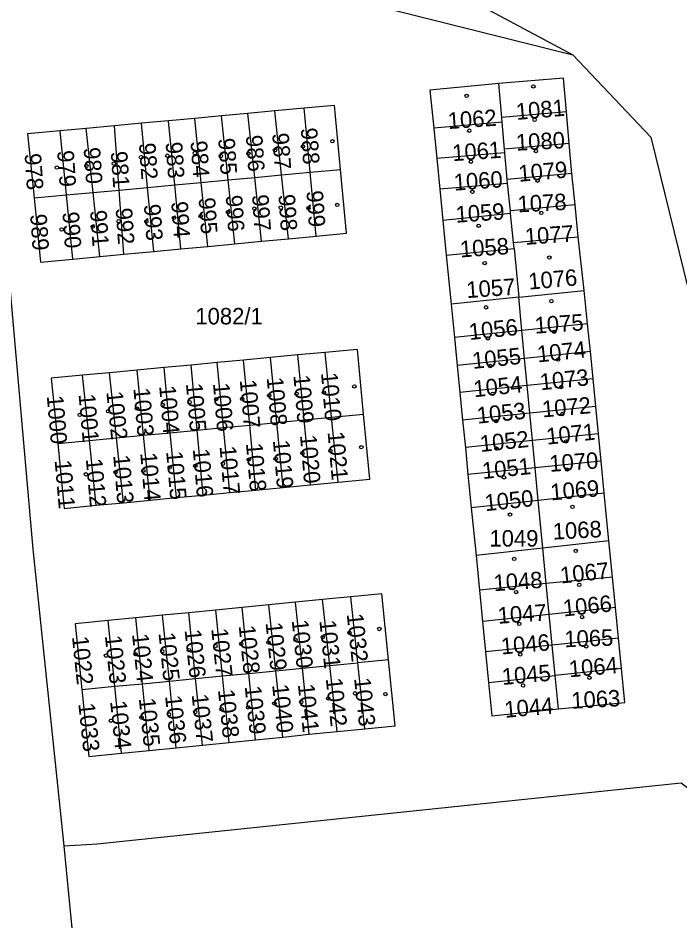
# Model space of a CAD drawing. Extents: x -869103 to -863415, y -1015889 to -1012477.
# Drawn here: x -866491.1 to -866422.9, y -1013922.4 to -1013829.3 of the extents above; entities that cross this region are included whole.
import ezdxf

# ---------------------------------------------------------------- set-up
doc = ezdxf.new("R2010")
doc.units = 0
for name, color, linetype in [('Hranice parcel', 7, 'Continuous'), ('Parcelní čísla', 7, 'Continuous'), ('Značky budov', 7, 'Continuous')]:
    doc.layers.add(name, color=color, linetype=linetype)

msp = doc.modelspace()

# ---------------------------------------------------------------- linework, layer by layer
at = {"layer": 'Hranice parcel'}
for p, q in [((-866467.18, -1013824.71), (-866433.93, -1013833.04)), ((-866441.25, -1013839.52), (-866441.57, -1013836.02)), ((-866464.66, -1013838.83), (-866467.43, -1013839.09)), ((-866461.63, -1013838.55), (-866464.66, -1013838.83)), ((-866463.96, -1013845.43), (-866464.66, -1013838.83)), ((-866461, -1013845.15), (-866461.63, -1013838.55)), ((-866434.58, -1013838.93), (-866441.25, -1013839.52)), ((-866434.29, -1013842.18), (-866434.58, -1013838.93)), ((-866475.62, -1013839.85), (-866478.42, -1013840.11)), ((-866472.92, -1013839.6), (-866475.62, -1013839.85)), ((-866474.98, -1013846.46), (-866475.62, -1013839.85)), ((-866470.16, -1013839.34), (-866472.92, -1013839.6)), ((-866472.24, -1013846.2), (-866472.92, -1013839.6)), ((-866467.43, -1013839.09), (-866470.16, -1013839.34)), ((-866469.47, -1013845.94), (-866470.16, -1013839.34)), ((-866466.72, -1013845.69), (-866467.43, -1013839.09)), ((-866441.21, -1013839.98), (-866448.27, -1013840.62)), ((-866441.21, -1013839.98), (-866441.25, -1013839.52)), ((-866440.96, -1013842.79), (-866441.21, -1013839.98)), ((-866484.1, -1013840.64), (-866486.78, -1013840.89)), ((-866486.14, -1013847.5), (-866486.78, -1013840.89)), ((-866481.2, -1013840.37), (-866484.1, -1013840.64)), ((-866483.4, -1013847.24), (-866484.1, -1013840.64)), ((-866478.42, -1013840.11), (-866481.2, -1013840.37)), ((-866480.71, -1013846.99), (-866481.2, -1013840.37)), ((-866477.78, -1013846.72), (-866478.42, -1013840.11)), ((-866448.27, -1013840.62), (-866447.96, -1013843.75)), ((-866434.29, -1013842.18), (-866440.96, -1013842.79)), ((-866434.03, -1013845.27), (-866434.29, -1013842.18)), ((-866440.94, -1013843.15), (-866447.96, -1013843.75)), ((-866440.94, -1013843.15), (-866440.96, -1013842.79)), ((-866440.7, -1013845.92), (-866440.94, -1013843.15)), ((-866447.96, -1013843.75), (-866447.65, -1013846.89)), ((-866466.72, -1013845.69), (-866463.96, -1013845.43)), ((-866463.96, -1013845.43), (-866461, -1013845.15)), ((-866463.26, -1013852.01), (-866463.96, -1013845.43)), ((-866461, -1013845.15), (-866457.87, -1013844.86)), ((-866460.38, -1013851.74), (-866461, -1013845.15)), ((-866434.03, -1013845.27), (-866440.7, -1013845.92)), ((-866433.7, -1013848.51), (-866434.03, -1013845.27)), ((-866477.78, -1013846.72), (-866474.98, -1013846.46)), ((-866474.98, -1013846.46), (-866472.24, -1013846.2)), ((-866474.35, -1013853.06), (-866474.98, -1013846.46)), ((-866472.24, -1013846.2), (-866469.47, -1013845.94)), ((-866471.57, -1013852.8), (-866472.24, -1013846.2)), ((-866469.47, -1013845.94), (-866466.72, -1013845.69)), ((-866468.78, -1013852.53), (-866469.47, -1013845.94)), ((-866466.02, -1013852.27), (-866466.72, -1013845.69)), ((-866440.67, -1013846.31), (-866447.65, -1013846.89)), ((-866440.67, -1013846.31), (-866440.7, -1013845.92)), ((-866440.37, -1013849.14), (-866440.67, -1013846.31)), ((-866486.14, -1013847.5), (-866483.4, -1013847.24)), ((-866483.4, -1013847.24), (-866480.71, -1013846.99)), ((-866482.7, -1013853.85), (-866483.4, -1013847.24)), ((-866480.71, -1013846.99), (-866477.78, -1013846.72)), ((-866480.22, -1013853.62), (-866480.71, -1013846.99)), ((-866477.14, -1013853.32), (-866477.78, -1013846.72)), ((-866447.65, -1013846.89), (-866447.33, -1013850.12)), ((-866489.49, -1013847.81), (-866486.14, -1013847.5)), ((-866485.49, -1013854.11), (-866486.14, -1013847.5)), ((-866433.7, -1013848.51), (-866440.37, -1013849.14)), ((-866440.34, -1013849.4), (-866440.37, -1013849.14)), ((-866433.38, -1013851.81), (-866433.7, -1013848.51)), ((-866440.34, -1013849.4), (-866447.33, -1013850.12)), ((-866447.33, -1013850.12), (-866446.98, -1013853.7)), ((-866440.05, -1013852.41), (-866440.34, -1013849.4)), ((-866466.02, -1013852.27), (-866463.26, -1013852.01)), ((-866463.26, -1013852.01), (-866460.38, -1013851.74)), ((-866440.05, -1013852.41), (-866433.38, -1013851.81)), ((-866432.74, -1013857.36), (-866433.38, -1013851.81)), ((-866474.35, -1013853.06), (-866471.57, -1013852.8)), ((-866471.57, -1013852.8), (-866468.78, -1013852.53)), ((-866468.78, -1013852.53), (-866466.02, -1013852.27)), ((-866439.99, -1013853.02), (-866440.05, -1013852.41)), ((-866485.49, -1013854.11), (-866482.7, -1013853.85)), ((-866482.7, -1013853.85), (-866480.22, -1013853.62)), ((-866480.22, -1013853.62), (-866477.14, -1013853.32)), ((-866477.14, -1013853.32), (-866474.35, -1013853.06)), ((-866446.98, -1013853.7), (-866439.99, -1013853.02)), ((-866446.98, -1013853.7), (-866446.48, -1013858.77)), ((-866439.99, -1013853.02), (-866439.51, -1013858.05)), ((-866439.51, -1013858.05), (-866432.74, -1013857.36)), ((-866432.4, -1013860.79), (-866432.74, -1013857.36)), ((-866439.51, -1013858.05), (-866446.48, -1013858.77)), ((-866439.18, -1013861.49), (-866439.51, -1013858.05)), ((-866446.48, -1013858.77), (-866446.14, -1013862.21)), ((-866432.4, -1013860.79), (-866439.18, -1013861.49)), ((-866432.12, -1013863.63), (-866432.4, -1013860.79)), ((-866439.18, -1013861.49), (-866446.14, -1013862.21)), ((-866446.14, -1013862.21), (-866445.85, -1013865.09)), ((-866438.9, -1013864.35), (-866439.18, -1013861.49)), ((-866462.29, -1013864), (-866465.11, -1013864.27)), ((-866459.46, -1013863.73), (-866462.29, -1013864)), ((-866461.64, -1013870.68), (-866462.29, -1013864)), ((-866458.8, -1013870.41), (-866459.46, -1013863.73)), ((-866432.12, -1013863.63), (-866438.9, -1013864.35)), ((-866431.84, -1013866.46), (-866432.12, -1013863.63)), ((-866473.3, -1013865.04), (-866476.08, -1013865.3)), ((-866470.59, -1013864.78), (-866473.3, -1013865.04)), ((-866472.68, -1013871.75), (-866473.3, -1013865.04)), ((-866467.88, -1013864.53), (-866470.59, -1013864.78)), ((-866469.94, -1013871.49), (-866470.59, -1013864.78)), ((-866465.11, -1013864.27), (-866467.88, -1013864.53)), ((-866467.25, -1013871.23), (-866467.88, -1013864.53)), ((-866464.46, -1013870.96), (-866465.11, -1013864.27)), ((-866438.9, -1013864.35), (-866445.85, -1013865.09)), ((-866445.85, -1013865.09), (-866445.58, -1013867.88)), ((-866438.63, -1013867.16), (-866438.9, -1013864.35)), ((-866481.69, -1013865.83), (-866484.48, -1013866.09)), ((-866478.86, -1013865.56), (-866481.69, -1013865.83)), ((-866480.98, -1013872.55), (-866481.69, -1013865.83)), ((-866476.08, -1013865.3), (-866478.86, -1013865.56)), ((-866478.19, -1013872.28), (-866478.86, -1013865.56)), ((-866475.44, -1013872.02), (-866476.08, -1013865.3)), ((-866483.78, -1013872.82), (-866484.48, -1013866.09)), ((-866431.84, -1013866.46), (-866438.63, -1013867.16)), ((-866431.56, -1013869.3), (-866431.84, -1013866.46)), ((-866438.63, -1013867.16), (-866445.58, -1013867.88)), ((-866445.58, -1013867.88), (-866445.3, -1013870.71)), ((-866438.36, -1013870), (-866438.63, -1013867.16)), ((-866431.56, -1013869.3), (-866438.36, -1013870)), ((-866431.28, -1013872.13), (-866431.56, -1013869.3)), ((-866464.46, -1013870.96), (-866461.64, -1013870.68)), ((-866461.64, -1013870.68), (-866458.8, -1013870.41)), ((-866460.99, -1013877.4), (-866461.64, -1013870.68)), ((-866458.8, -1013870.41), (-866455.5, -1013870.09)), ((-866458.14, -1013877.12), (-866458.8, -1013870.41)), ((-866438.36, -1013870), (-866445.3, -1013870.71)), ((-866445.3, -1013870.71), (-866445.01, -1013873.55)), ((-866438.09, -1013872.83), (-866438.36, -1013870)), ((-866472.68, -1013871.75), (-866469.94, -1013871.49)), ((-866469.94, -1013871.49), (-866467.25, -1013871.23)), ((-866469.29, -1013878.19), (-866469.94, -1013871.49)), ((-866467.25, -1013871.23), (-866464.46, -1013870.96)), ((-866466.61, -1013877.93), (-866467.25, -1013871.23)), ((-866463.81, -1013877.66), (-866464.46, -1013870.96)), ((-866483.78, -1013872.82), (-866480.98, -1013872.55)), ((-866480.98, -1013872.55), (-866478.19, -1013872.28)), ((-866480.27, -1013879.24), (-866480.98, -1013872.55)), ((-866478.19, -1013872.28), (-866475.44, -1013872.02)), ((-866477.52, -1013878.97), (-866478.19, -1013872.28)), ((-866475.44, -1013872.02), (-866472.68, -1013871.75)), ((-866474.8, -1013878.71), (-866475.44, -1013872.02)), ((-866472.06, -1013878.45), (-866472.68, -1013871.75)), ((-866431.28, -1013872.13), (-866438.09, -1013872.83)), ((-866431, -1013874.97), (-866431.28, -1013872.13)), ((-866487.05, -1013873.14), (-866483.78, -1013872.82)), ((-866483.09, -1013879.5), (-866483.78, -1013872.82)), ((-866438.09, -1013872.83), (-866445.01, -1013873.55)), ((-866437.82, -1013875.64), (-866438.09, -1013872.83)), ((-866445.01, -1013873.55), (-866444.74, -1013876.33)), ((-866431, -1013874.97), (-866437.82, -1013875.64)), ((-866430.68, -1013878.25), (-866431, -1013874.97)), ((-866437.82, -1013875.64), (-866444.74, -1013876.33)), ((-866437.5, -1013879), (-866437.82, -1013875.64)), ((-866460.99, -1013877.4), (-866458.14, -1013877.12)), ((-866444.74, -1013876.33), (-866444.4, -1013879.76)), ((-866469.29, -1013878.19), (-866466.61, -1013877.93)), ((-866466.61, -1013877.93), (-866463.81, -1013877.66)), ((-866463.81, -1013877.66), (-866460.99, -1013877.4)), ((-866480.27, -1013879.24), (-866477.52, -1013878.97)), ((-866477.52, -1013878.97), (-866474.8, -1013878.71)), ((-866474.8, -1013878.71), (-866472.06, -1013878.45)), ((-866472.06, -1013878.45), (-866469.29, -1013878.19)), ((-866437.5, -1013879), (-866444.4, -1013879.76)), ((-866430.68, -1013878.25), (-866437.5, -1013879)), ((-866437.02, -1013883.93), (-866437.5, -1013879)), ((-866430.2, -1013883.17), (-866430.68, -1013878.25)), ((-866483.09, -1013879.5), (-866480.27, -1013879.24)), ((-866444.4, -1013879.76), (-866443.91, -1013884.69)), ((-866430.2, -1013883.17), (-866437.02, -1013883.93)), ((-866429.83, -1013886.9), (-866430.2, -1013883.17)), ((-866437.02, -1013883.93), (-866443.91, -1013884.69)), ((-866436.67, -1013887.58), (-866437.02, -1013883.93)), ((-866443.91, -1013884.69), (-866443.56, -1013888.27)), ((-866429.83, -1013886.9), (-866436.67, -1013887.58)), ((-866429.52, -1013890.03), (-866429.83, -1013886.9)), ((-866436.67, -1013887.58), (-866443.56, -1013888.27)), ((-866443.56, -1013888.27), (-866443.24, -1013891.5)), ((-866436.36, -1013890.76), (-866436.67, -1013887.58)), ((-866459.73, -1013889.23), (-866462.53, -1013889.5)), ((-866456.81, -1013888.94), (-866459.73, -1013889.23)), ((-866458.99, -1013896.03), (-866459.73, -1013889.23)), ((-866456.09, -1013895.75), (-866456.81, -1013888.94)), ((-866468.02, -1013890.04), (-866470.74, -1013890.31)), ((-866465.27, -1013889.77), (-866468.02, -1013890.04)), ((-866467.34, -1013896.84), (-866468.02, -1013890.04)), ((-866462.53, -1013889.5), (-866465.27, -1013889.77)), ((-866464.56, -1013896.57), (-866465.27, -1013889.77)), ((-866461.82, -1013896.31), (-866462.53, -1013889.5)), ((-866429.52, -1013890.03), (-866436.36, -1013890.76)), ((-866429.21, -1013893.22), (-866429.52, -1013890.03)), ((-866478.98, -1013891.12), (-866481.83, -1013891.4)), ((-866476.24, -1013890.85), (-866478.98, -1013891.12)), ((-866478.3, -1013897.9), (-866478.98, -1013891.12)), ((-866473.51, -1013890.58), (-866476.24, -1013890.85)), ((-866475.53, -1013897.63), (-866476.24, -1013890.85)), ((-866470.74, -1013890.31), (-866473.51, -1013890.58)), ((-866472.82, -1013897.37), (-866473.51, -1013890.58)), ((-866470.06, -1013897.1), (-866470.74, -1013890.31)), ((-866436.36, -1013890.76), (-866443.24, -1013891.5)), ((-866436.06, -1013893.92), (-866436.36, -1013890.76)), ((-866481.16, -1013898.17), (-866481.83, -1013891.4)), ((-866443.24, -1013891.5), (-866442.93, -1013894.63)), ((-866436.06, -1013893.92), (-866442.93, -1013894.63)), ((-866429.21, -1013893.22), (-866436.06, -1013893.92)), ((-866435.76, -1013897.05), (-866436.06, -1013893.92)), ((-866428.9, -1013896.33), (-866429.21, -1013893.22)), ((-866442.93, -1013894.63), (-866442.62, -1013897.77)), ((-866458.99, -1013896.03), (-866456.09, -1013895.75)), ((-866452.93, -1013895.45), (-866456.09, -1013895.75)), ((-866455.37, -1013902.55), (-866456.09, -1013895.75)), ((-866467.34, -1013896.84), (-866464.56, -1013896.57)), ((-866464.56, -1013896.57), (-866461.82, -1013896.31)), ((-866463.84, -1013903.4), (-866464.56, -1013896.57)), ((-866461.82, -1013896.31), (-866458.99, -1013896.03)), ((-866461.11, -1013903.12), (-866461.82, -1013896.31)), ((-866458.24, -1013902.84), (-866458.99, -1013896.03)), ((-866428.9, -1013896.33), (-866435.76, -1013897.05)), ((-866478.3, -1013897.9), (-866475.53, -1013897.63)), ((-866475.53, -1013897.63), (-866472.82, -1013897.37)), ((-866474.82, -1013904.5), (-866475.53, -1013897.63)), ((-866472.82, -1013897.37), (-866470.06, -1013897.1)), ((-866472.12, -1013904.23), (-866472.82, -1013897.37)), ((-866470.06, -1013897.1), (-866467.34, -1013896.84)), ((-866469.38, -1013903.95), (-866470.06, -1013897.1)), ((-866466.66, -1013903.68), (-866467.34, -1013896.84)), ((-866442.62, -1013897.77), (-866435.76, -1013897.05)), ((-866435.42, -1013900.51), (-866435.76, -1013897.05)), ((-866484.55, -1013898.5), (-866481.16, -1013898.17)), ((-866481.16, -1013898.17), (-866478.3, -1013897.9)), ((-866480.48, -1013905.06), (-866481.16, -1013898.17)), ((-866477.61, -1013904.78), (-866478.3, -1013897.9)), ((-866463.84, -1013903.4), (-866461.11, -1013903.12)), ((-866461.11, -1013903.12), (-866458.24, -1013902.84)), ((-866458.24, -1013902.84), (-866455.37, -1013902.55)), ((-866474.82, -1013904.5), (-866472.12, -1013904.23)), ((-866472.12, -1013904.23), (-866469.38, -1013903.95)), ((-866469.38, -1013903.95), (-866466.66, -1013903.68)), ((-866466.66, -1013903.68), (-866463.84, -1013903.4)), ((-866480.48, -1013905.06), (-866477.61, -1013904.78)), ((-866477.61, -1013904.78), (-866474.82, -1013904.5)), ((-866479.31, -1013987.71), (-866486.37, -1013914.62))]:
    msp.add_line(p, q, dxfattribs=at)
for points in [[(-866491.13, -1013799.65), (-866474.29, -1013811.45), (-866433.93, -1013833.04)], [(-866433.93, -1013833.04), (-866425.87, -1013841.53), (-866420.57, -1013863.24)], [(-866441.57, -1013836.02), (-866448.66, -1013836.69), (-866448.27, -1013840.62)], [(-866434.58, -1013838.93), (-866434.89, -1013835.45), (-866441.57, -1013836.02)], [(-866457.87, -1013844.86), (-866458.49, -1013838.26), (-866461.63, -1013838.55)], [(-866486.37, -1013914.62), (-866489.58, -1013884.02), (-866493.46, -1013840.16)], [(-866486.78, -1013840.89), (-866490.15, -1013841.2), (-866489.49, -1013847.81)], [(-866460.38, -1013851.74), (-866457.26, -1013851.44), (-866457.87, -1013844.86)], [(-866489.49, -1013847.81), (-866488.82, -1013854.43), (-866485.49, -1013854.11)], [(-866455.5, -1013870.09), (-866456.14, -1013863.42), (-866459.46, -1013863.73)], [(-866484.48, -1013866.09), (-866487.72, -1013866.4), (-866487.05, -1013873.14)], [(-866458.14, -1013877.12), (-866454.86, -1013876.81), (-866455.5, -1013870.09)], [(-866487.05, -1013873.14), (-866486.39, -1013879.82), (-866483.09, -1013879.5)], [(-866452.93, -1013895.45), (-866453.61, -1013888.63), (-866456.81, -1013888.94)], [(-866481.83, -1013891.4), (-866485.24, -1013891.73), (-866484.55, -1013898.5)], [(-866455.37, -1013902.55), (-866452.26, -1013902.24), (-866452.93, -1013895.45)], [(-866435.42, -1013900.51), (-866428.56, -1013899.83), (-866428.9, -1013896.33)], [(-866484.55, -1013898.5), (-866483.85, -1013905.4), (-866480.48, -1013905.06)], [(-866442.62, -1013897.77), (-866442.28, -1013901.2), (-866435.42, -1013900.51)], [(-866486.37, -1013914.62), (-866482.98, -1013914.41), (-866422.75, -1013908.14), (-866404.85, -1013921.93)]]:
    msp.add_lwpolyline(points, dxfattribs=at)
at = {"layer": 'Značky budov'}
for centre in [(-866437.997, -1013836.309), (-866444.877, -1013837.289), (-866437.867, -1013839.749), (-866444.607, -1013840.869), (-866458.717, -1013841.959), (-866464.637, -1013842.889), (-866461.757, -1013842.489), (-866478.457, -1013843.599), (-866475.747, -1013843.449), (-866472.907, -1013843.169), (-866470.227, -1013843.479), (-866467.377, -1013843.229), (-866437.737, -1013842.969), (-866487.137, -1013844.679), (-866484.087, -1013844.509), (-866481.257, -1013844.259), (-866444.437, -1013844.069), (-866437.557, -1013846.029), (-866444.287, -1013847.189), (-866458.217, -1013848.529), (-866469.487, -1013849.269), (-866466.757, -1013848.909), (-866464.037, -1013848.809), (-866461.197, -1013848.849), (-866437.187, -1013849.349), (-866480.767, -1013850.199), (-866477.897, -1013850.239), (-866475.057, -1013849.869), (-866472.307, -1013849.679), (-866486.647, -1013851.059), (-866483.437, -1013850.759), (-866443.637, -1013850.669), (-866436.347, -1013853.959), (-866443.017, -1013854.529), (-866436.137, -1013858.449), (-866442.877, -1013859.089), (-866442.687, -1013862.289), (-866435.847, -1013861.609), (-866442.437, -1013865.139), (-866435.447, -1013864.479), (-866462.417, -1013867.999), (-866459.597, -1013867.859), (-866456.457, -1013867.239), (-866442.177, -1013867.999), (-866435.117, -1013867.309), (-866473.457, -1013868.869), (-866470.697, -1013868.549), (-866468.027, -1013868.529), (-866465.227, -1013868.169), (-866481.847, -1013869.809), (-866478.867, -1013869.529), (-866476.217, -1013869.159), (-866484.777, -1013870.179), (-866441.837, -1013870.819), (-866435.017, -1013870.089), (-866455.737, -1013873.519), (-866441.807, -1013873.659), (-866434.617, -1013872.919), (-866461.807, -1013874.119), (-866458.927, -1013873.889), (-866472.857, -1013875.429), (-866470.007, -1013875.209), (-866467.347, -1013874.789), (-866464.567, -1013874.699), (-866484.137, -1013876.309), (-866481.077, -1013876.099), (-866478.217, -1013875.939), (-866475.507, -1013875.609), (-866434.517, -1013875.819), (-866441.027, -1013876.629), (-866433.957, -1013879.669), (-866440.407, -1013880.459), (-866433.627, -1013884.209), (-866439.977, -1013885.039), (-866439.777, -1013888.459), (-866433.267, -1013887.709), (-866432.977, -1013891.029), (-866453.877, -1013892.259), (-866439.447, -1013891.739), (-866459.717, -1013893.099), (-866456.967, -1013892.649), (-866470.777, -1013894.019), (-866468.117, -1013893.789), (-866465.307, -1013893.659), (-866462.527, -1013893.389), (-866432.547, -1013894.059), (-866482.077, -1013895.009), (-866479.017, -1013894.869), (-866476.267, -1013894.559), (-866473.517, -1013894.439), (-866439.347, -1013894.879), (-866432.217, -1013897.289), (-866439.057, -1013898.089), (-866459.147, -1013899.419), (-866456.377, -1013898.899), (-866453.257, -1013898.969), (-866470.157, -1013900.539), (-866467.407, -1013900.349), (-866464.707, -1013899.949), (-866461.937, -1013899.789), (-866478.407, -1013901.389), (-866475.577, -1013901.059), (-866472.867, -1013900.819), (-866481.557, -1013901.719)]:
    msp.add_circle(centre, 0.175, dxfattribs=at)

# ---------------------------------------------------------------- texts
at = {"layer": 'Parcelní čísla'}
for s, rotation, p in [('1081', 5, (-866439.725, -1013839.766)), ('1062', 4, (-866446.77, -1013840.707)), ('988', 274, (-866461.987, -1013840.619)), ('985', 274, (-866470.497, -1013841.679)), ('986', 274, (-866467.647, -1013841.369)), ('987', 274, (-866464.927, -1013841.149)), ('1080', 3, (-866439.755, -1013842.938)), ('980', 274, (-866484.377, -1013842.639)), ('982', 274, (-866478.667, -1013842.179)), ('983', 274, (-866475.917, -1013842.079)), ('984', 274, (-866473.347, -1013841.959)), ('1061', 4, (-866446.31, -1013844.017)), ('978', 274, (-866490.467, -1013843.259)), ('979', 274, (-866487.097, -1013842.949)), ('981', 274, (-866481.577, -1013843.039)), ('1079', 5, (-866439.465, -1013846.146)), ('1060', 4, (-866446.15, -1013847.057)), ('999', 274, (-866461.397, -1013847.089)), ('1078', 3, (-866439.585, -1013849.298)), ('994', 274, (-866475.337, -1013848.209)), ('995', 274, (-866472.517, -1013847.809)), ('996', 274, (-866469.727, -1013847.559)), ('997', 274, (-866467.007, -1013847.499)), ('998', 274, (-866464.287, -1013847.479)), ('1059', 4, (-866445.96, -1013850.367)), ('990', 274, (-866486.557, -1013849.279)), ('991', 274, (-866483.707, -1013849.109)), ('992', 274, (-866481.077, -1013848.879)), ('993', 274, (-866478.157, -1013848.489)), ('989', 274, (-866489.887, -1013849.509)), ('1077', 4, (-866438.82, -1013852.647)), ('1058', 4, (-866445.51, -1013853.947)), ('1076', 5, (-866438.445, -1013857.266)), ('1057', 4, (-866444.85, -1013858.137)), ('1056', 6, (-866444.561, -1013862.465)), ('1075', 4, (-866437.81, -1013861.807)), ('1055', 6, (-866444.221, -1013865.445)), ('1074', 6, (-866437.531, -1013864.775)), ('1010', 275, (-866459.896, -1013865.854)), ('1073', 6, (-866437.241, -1013867.645)), ('1007', 275, (-866468.276, -1013866.594)), ('1008', 275, (-866465.496, -1013866.344)), ('1009', 275, (-866462.746, -1013866.104)), ('1054', 6, (-866444.091, -1013868.365)), ('1002', 276, (-866482.035, -1013867.808)), ('1003', 275, (-866479.246, -1013867.434)), ('1004', 275, (-866476.586, -1013867.204)), ('1005', 275, (-866473.826, -1013866.964)), ('1006', 275, (-866471.036, -1013866.934)), ('1000', 275, (-866488.176, -1013868.224)), ('1001', 275, (-866484.896, -1013868.054)), ('1072', 5, (-866437.035, -1013870.446)), ('1053', 6, (-866443.741, -1013871.095)), ('1071', 6, (-866436.581, -1013873.255)), ('1020', 275, (-866462.066, -1013872.284)), ('1021', 275, (-866459.216, -1013871.954)), ('1052', 6, (-866443.421, -1013874.015)), ('1018', 275, (-866467.636, -1013873.134)), ('1019', 275, (-866464.856, -1013872.824)), ('1014', 275, (-866478.536, -1013874.124)), ('1015', 275, (-866475.866, -1013873.964)), ('1016', 275, (-866473.116, -1013873.714)), ('1017', 275, (-866470.356, -1013873.434)), ('1070', 4, (-866436.29, -1013876.057)), ('1011', 275, (-866487.366, -1013874.884)), ('1012', 275, (-866484.146, -1013874.734)), ('1013', 275, (-866481.326, -1013874.364)), ('1051', 6, (-866443.201, -1013876.805)), ('1069', 5, (-866436.175, -1013879.006)), ('1050', 6, (-866442.941, -1013880.115)), ('1068', 3, (-866435.955, -1013883.048)), ('1067', 6, (-866435.151, -1013887.575)), ('1048', 4, (-866442.05, -1013888.367)), ('1066', 6, (-866434.861, -1013890.975)), ('1047', 4, (-866441.62, -1013891.727)), ('1032', 276, (-866457.245, -1013890.728)), ('1028', 276, (-866468.385, -1013891.938)), ('1029', 276, (-866465.615, -1013891.628)), ('1030', 276, (-866462.915, -1013891.368)), ('1031', 276, (-866460.065, -1013891.398)), ('1023', 276, (-866482.185, -1013892.968)), ('1024', 276, (-866479.385, -1013892.798)), ('1025', 276, (-866476.655, -1013892.678)), ('1026', 276, (-866473.965, -1013892.368)), ('1027', 276, (-866471.215, -1013892.248)), ('1046', 5, (-866441.275, -1013894.896)), ('1065', 2, (-866434.78, -1013894.149)), ('1022', 276, (-866485.575, -1013893.068)), ('1064', 5, (-866434.265, -1013897.246)), ('1045', 5, (-866441.175, -1013898.036)), ('1042', 276, (-866459.405, -1013897.378)), ('1043', 276, (-866456.485, -1013897.348)), ('1038', 276, (-866470.525, -1013898.548)), ('1039', 276, (-866467.765, -1013898.188)), ('1040', 276, (-866464.935, -1013898.028)), ('1041', 276, (-866462.285, -1013897.988)), ('1063', 3, (-866434.045, -1013900.488)), ('1035', 276, (-866478.685, -1013899.428)), ('1036', 276, (-866475.975, -1013899.168)), ('1037', 276, (-866473.235, -1013899.028)), ('1044', 5, (-866440.915, -1013901.426)), ('1033', 276, (-866484.925, -1013899.958)), ('1034', 276, (-866481.645, -1013899.718))]:
    msp.add_text(s, height=1.7, rotation=rotation, dxfattribs=at).set_placement(p)
for s, p in [('1082/1', (-866472.855, -1013860.85)), ('1049', (-866442.53, -1013883.76))]:
    msp.add_text(s, height=1.7, dxfattribs=at).set_placement(p)

doc.saveas('drawing.dxf')
